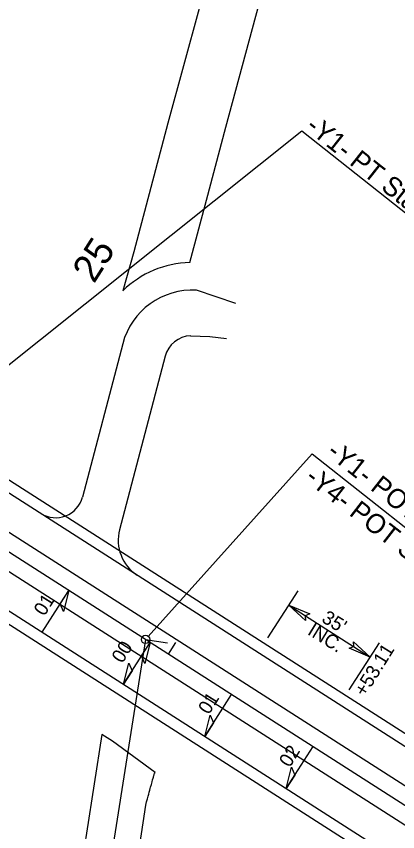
# Model space of a CAD drawing. Extents: x 1778969 to 1790720, y 807089 to 817794.
# Drawn here: x 1782702.6 to 1782840.8, y 814148.6 to 814443.8 of the extents above; entities that cross this region are included whole.
import ezdxf

# ---------------------------------------------------------------- set-up
doc = ezdxf.new("R2010")
doc.units = 0
for name, color, linetype in [('Prop Dimension', 7, 'Continuous'), ('Prop Dimension Text', 7, 'Continuous'), ('Prop EOT', 7, 'Continuous'), ('Prop Horizontal Alignment', 7, 'Continuous'), ('Prop Horizontal Alignment Station Label', 7, 'Continuous'), ('Prop Horizontal Alignment Tick Label', 7, 'Continuous'), ('Prop Horizontal Alignment Tick Large', 7, 'Continuous'), ('Prop Horizontal Alignment Tick Small', 7, 'Continuous'), ('Prop Lane Lines', 7, 'Continuous'), ('Prop Paved Shoulder', 7, 'Continuous'), ('Prop Rem of Exist Asph Pvmt', 7, 'Continuous'), ('Prop Superelevation  Arrow CELL', 7, 'Continuous'), ('Prop Superelevation Label', 7, 'Continuous'), ('Prop Terminator CELL', 7, 'Continuous')]:
    doc.layers.add(name, color=color, linetype=linetype)

msp = doc.modelspace()

# ---------------------------------------------------------------- linework, layer by layer
at = {"layer": 'Prop Dimension'}
for p, q in [((1782793.79, 814218.82), (1782804.69, 814235.86)), ((1782801.34, 814230.62), (1782830.82, 814211.76)), ((1782753.4, 814217.59), (1782753.4, 814217.59)), ((1782823.28, 814199.96), (1782834.17, 814217.01))]:
    msp.add_line(p, q, dxfattribs=at)
at = {"layer": 'Prop EOT'}
for p, q in [((1782782.19, 814339.9), (1782767.92, 814344.62)), ((1782765.76, 814328.18), (1782765.84, 814328.18)), ((1782765.76, 814328.18), (1782772.78, 814327.95)), ((1782772.78, 814327.95), (1782778.78, 814327.13)), ((1782741.19, 814325.28), (1782726.58, 814269.71)), ((1782756.54, 814320.73), (1782740.03, 814257.95)), ((1782662.57, 814295.14), (1783159.17, 813977.59)), ((1782643.17, 814264.81), (1783139.78, 813947.26))]:
    msp.add_line(p, q, dxfattribs=at)
for centre, radius, start, end in [((1780718.82, 815764.26), 2309.25, 324.08998, 332.9908), ((1780718.82, 815764.26), 2350.75, 323.92554, 332.9908), ((1782766.34, 814318.67), 26, 86.517, 165.2667), ((1782766.21, 814318.19), 10, 92.5717, 165.2667), ((1782716.91, 814272.26), 10, 237.4039, 345.2667), ((1782754.54, 814254.13), 15, 165.2667, 237.4039)]:
    msp.add_arc(centre, radius, start, end, dxfattribs=at)
at = {"layer": 'Prop Horizontal Alignment'}
for p, q in [((1782652.87, 814279.97), (1783782.01, 813557.97)), ((1782749.45, 814218.21), (1782703.38, 813926.21))]:
    msp.add_line(p, q, dxfattribs=at)
msp.add_arc((1780718.82, 815764.26), 2330, 324.08998, 342.60824, dxfattribs=at)
at = {"layer": 'Prop Horizontal Alignment Station Label'}
for p, q in [((1782653.98, 814280.98), (1782806.02, 814402.42)), ((1782806.02, 814402.42), (1782889.07, 814336.67)), ((1782750.46, 814219.33), (1782809.85, 814285.43)), ((1782809.85, 814285.43), (1782900.77, 814213.44))]:
    msp.add_line(p, q, dxfattribs=at)
msp.add_circle((1782749.45, 814218.21), 1.5, dxfattribs=at)
msp.add_circle((1782749.45, 814218.21), 1.5, dxfattribs=at)
at = {"layer": 'Prop Horizontal Alignment Tick Large'}
msp.add_line((1782749.45, 814218.21), (1782757.36, 814216.97), dxfattribs=at)
at = {"layer": 'Prop Horizontal Alignment Tick Small'}
msp.add_line((1782757.72, 814212.93), (1782760.41, 814217.14), dxfattribs=at)
at = {"layer": 'Prop Lane Lines'}
for p, q in [((1782656.1, 814285.03), (1783144.28, 813972.87)), ((1782649.64, 814274.92), (1783146.07, 813957.48))]:
    msp.add_line(p, q, dxfattribs=at)
for radius, end in [(2321.25, 333.45226), (2333.25, 332.9908), (2338.75, 332.9908)]:
    msp.add_arc((1780718.82, 815764.26), radius, 324.13824, end, dxfattribs=at)
at = {"layer": 'Prop Paved Shoulder'}
for p, q in [((1782664.72, 814298.51), (1783161.32, 813980.96)), ((1782641.02, 814261.44), (1783137.62, 813943.89))]:
    msp.add_line(p, q, dxfattribs=at)
for radius, start in [(2305.25, 324.08998), (2354.75, 323.92554)]:
    msp.add_arc((1780718.82, 815764.26), radius, start, 332.9908, dxfattribs=at)
at = {"layer": 'Prop Rem of Exist Asph Pvmt'}
for p, q in [((1782737.51, 814181.33), (1782733.63, 814183.8)), ((1782752.89, 814170.04), (1782737.51, 814181.33))]:
    msp.add_line(p, q, dxfattribs=at)
for points in [[(1782778.05, 814480.5), (1782768.85, 814446.71), (1782757.57, 814405.12), (1782745.18, 814358.58), (1782741.23, 814344.46)], [(1782765.49, 814354.66), (1782771.5, 814377.24), (1782778.49, 814403.65), (1782790.59, 814448.3), (1782798.82, 814477.74), (1782798.85, 814477.84)], [(1782733.63, 814183.8), (1782728.02, 814148.04), (1782723.78, 814121.03)], [(1782743.39, 814117.93), (1782743.83, 814120.73), (1782749.51, 814158.26)]]:
    msp.add_lwpolyline(points, dxfattribs=at)
msp.add_arc((1782766.34, 814318.67), 36, 91.344, 134.2251, dxfattribs=at)
msp.add_open_spline([(1782749.51, 814158.26), (1782750.44, 814161.64), (1782751.38, 814165.02), (1782752.31, 814168.4), (1782752.47, 814168.96), (1782752.66, 814169.51), (1782752.89, 814170.04)], degree=3, dxfattribs=at)
at = {"layer": 'Prop Superelevation  Arrow CELL'}
for p, q in [((1782711.98, 814220.81), (1782721.67, 814235.98)), ((1782741.46, 814201.96), (1782751.16, 814217.12)), ((1782770.95, 814183.1), (1782780.65, 814198.27)), ((1782800.44, 814164.25), (1782810.14, 814179.41))]:
    msp.add_line(p, q, dxfattribs=at)
for points in [[(1782721.67, 814235.98), (1782719.74, 814228.31), (1782718.56, 814231.1)], [(1782751.16, 814217.12), (1782749.23, 814209.45), (1782748.05, 814212.25)], [(1782741.46, 814201.96), (1782743.4, 814209.62), (1782744.58, 814206.83)], [(1782770.95, 814183.1), (1782772.89, 814190.77), (1782774.07, 814187.97)], [(1782800.44, 814164.25), (1782802.37, 814171.91), (1782803.55, 814169.12)]]:
    msp.add_lwpolyline(points, close=True, dxfattribs=at)
at = {"layer": 'Prop Terminator CELL'}
for points in [[(1782807.41, 814225.08), (1782801.34, 814230.62), (1782808.97, 814227.45), (1782807.33, 814226.79)], [(1782824.8, 814217.35), (1782830.82, 814211.76), (1782823.21, 814215), (1782824.87, 814215.64)]]:
    msp.add_lwpolyline(points, close=True, dxfattribs=at)

# ---------------------------------------------------------------- texts
at = {"layer": 'Prop Dimension Text'}
for s, rotation, p in [("35'", 328.4002, (1782812.89, 814224.8)), ('INC.', 328.4002, (1782807.79, 814220.24)), ('+53.11', 58.0375, (1782828.9, 814197.16))]:
    msp.add_text(s, height=5, rotation=rotation, dxfattribs=at).set_placement(p)
at = {"layer": 'Prop Horizontal Alignment Station Label'}
for s, rotation, p in [('-Y1- PT Sta.  24+75.55', 321.5598, (1782807.09, 814403.05)), ('-Y1- POT Sta. 25+90.19 =', 321.6309, (1782814.65, 814285.21)), ('-Y4- POT Sta.  10+00.00', 322.1355, (1782806.85, 814275.91))]:
    msp.add_text(s, height=7, rotation=rotation, dxfattribs=at).set_placement(p)
at = {"layer": 'Prop Horizontal Alignment Tick Label'}
msp.add_text('25', height=10, rotation=57.4039, dxfattribs=at).set_placement((1782730.79, 814346.8))
at = {"layer": 'Prop Superelevation Label'}
for s, p in [('01', (1782712.84, 814226.4)), ('00', (1782741.05, 814209.29)), ('01', (1782772.41, 814190.74)), ('02', (1782801.71, 814171.59))]:
    msp.add_text(s, height=5, rotation=57.9989, dxfattribs=at).set_placement(p)

doc.saveas('drawing.dxf')
